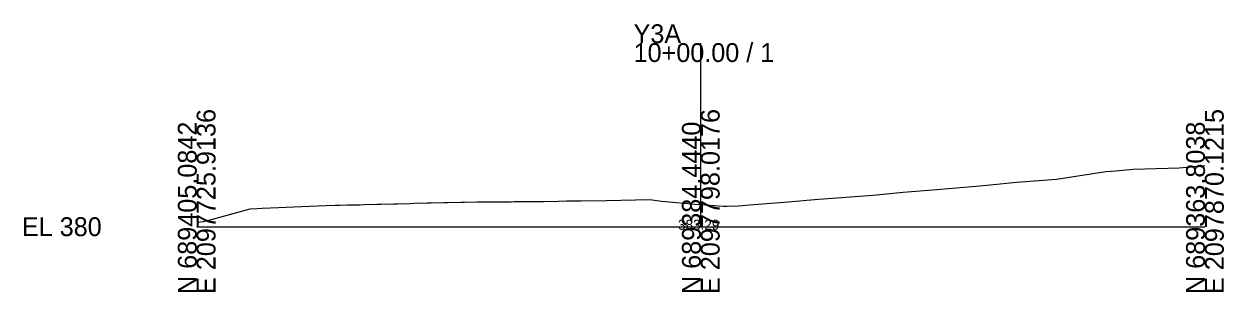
# Model space of a CAD drawing. Extents: x -26 to 2453, y -10 to 1032.
# Drawn here: x -25.7 to 152.8, y -9.7 to 30.1 of the extents above; entities that cross this region are included whole.
import ezdxf

# ---------------------------------------------------------------- set-up
doc = ezdxf.new("R2010")
doc.units = 0
for name, color, linetype in [('Exist Cross Section Cell', 7, 'Continuous'), ('Exist XS Center Line Elevation Label', 7, 'Continuous'), ('Exist XS Ground Line', 7, 'Continuous')]:
    doc.layers.add(name, color=color, linetype=linetype)

msp = doc.modelspace()

# ---------------------------------------------------------------- linework, layer by layer
at = {"layer": 'Exist Cross Section Cell'}
for p, q in [((75, 0), (75, 27.26)), ((0, 0), (75, 0)), ((75, 0), (150, 0))]:
    msp.add_line(p, q, dxfattribs=at)
at = {"layer": 'Exist XS Ground Line'}
msp.add_lwpolyline([(0, 0.68), (1.06, 0.75), (1.99, 1.02), (7.97, 2.66), (9.02, 2.7), (9.75, 2.73), (12.17, 2.84), (17.9, 3.08), (20.6, 3.21), (21.27, 3.21), (22.42, 3.24), (23.57, 3.26), (24.28, 3.27), (24.98, 3.29), (26.78, 3.33), (27.46, 3.35), (29.28, 3.39), (29.93, 3.41), (31.78, 3.45), (32.4, 3.47), (34.28, 3.52), (34.88, 3.53), (36.78, 3.6), (37.35, 3.6), (39.28, 3.64), (39.83, 3.65), (41.78, 3.67), (42.3, 3.67), (44.28, 3.69), (44.77, 3.69), (46.78, 3.71), (47.25, 3.72), (49.28, 3.73), (49.63, 3.74), (51.71, 3.76), (53.83, 3.8), (55.04, 3.82), (57.15, 3.85), (60.97, 3.91), (67.41, 4.02), (69.14, 3.8), (69.74, 3.75), (74.18, 3.35), (75, 3.29), (78.38, 3.04), (78.89, 3.06), (80.54, 3.12), (81.19, 3.16), (82.24, 3.25), (88.02, 3.67), (91.94, 4.03), (92.51, 4.09), (93.23, 4.15), (100.61, 4.68), (102.13, 4.85), (105.11, 5.13), (110.12, 5.54), (116.52, 6.09), (118.03, 6.22), (121.99, 6.61), (127.91, 7.05), (135.28, 8.19), (136.76, 8.32), (139.32, 8.55), (146.18, 8.76), (150, 9.09)], dxfattribs=at)

# ---------------------------------------------------------------- texts
at = {"layer": 'Exist Cross Section Cell'}
for s, p in [('Y3A', (65, 27.26)), ('10+00.00 / 1', (65, 24.46)), ('EL 380', (-26, -1.4))]:
    msp.add_text(s, height=2.8, dxfattribs=at).set_placement(p)
for s, p in [('E 2097725.9136', (2.8, -10)), ('E 2097798.0176', (77.8, -10)), ('E 2097870.1215', (152.8, -10)), ('N 689405.0842', (0, -10)), ('N 689384.4440', (75, -10)), ('N 689363.8038', (150, -10))]:
    msp.add_text(s, height=2.8, rotation=90, dxfattribs=at).set_placement(p)
at = {"layer": 'Exist XS Center Line Elevation Label'}
msp.add_text('383.29', height=1.5, dxfattribs=at).set_placement((71.62, -0.46))

doc.saveas('drawing.dxf')
